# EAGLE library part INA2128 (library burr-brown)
Dual Instrumentation Amplifier Low Power
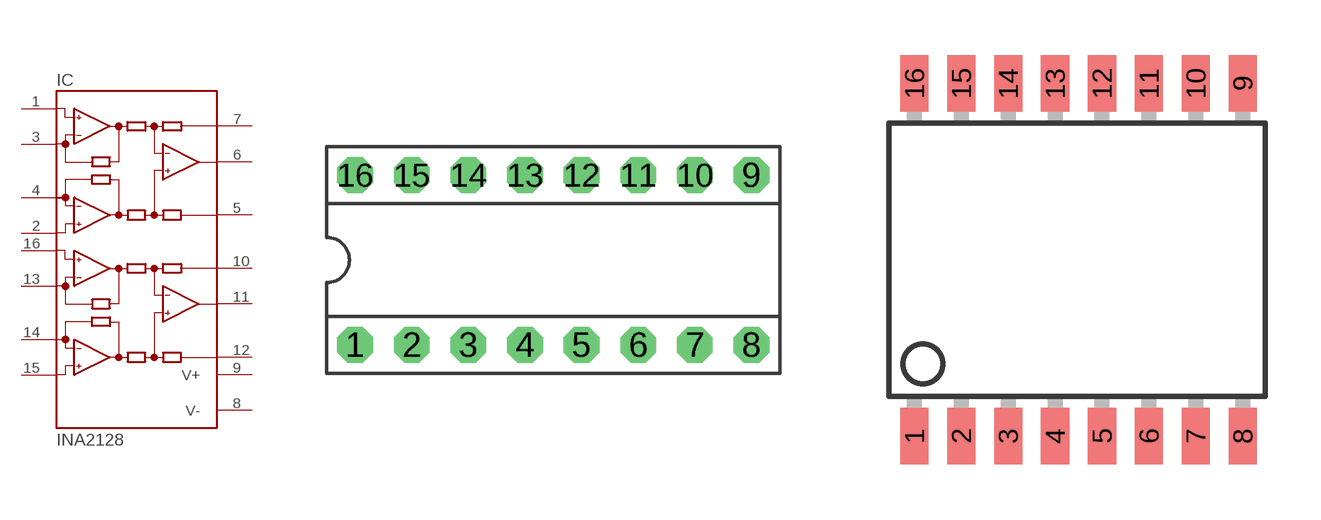
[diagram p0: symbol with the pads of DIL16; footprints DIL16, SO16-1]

Designator prefix IC

## INA2128P (OC_FARNELL: unknown; OC_NEWARK: unknown)  [DIL16]
1  INA-  in
2  INA+  in
3  RGA  pas
4  RGA  pas
5  REFA  in
6  VOA  out
7  SENSEA  in
8  V-  pwr
9  V+  pwr
10  SENSEB  in
11  VOB  out
12  REFB  in
13  RGB  pas
14  RGB  pas
15  INB+  in
16  INB-  in

## INA2128U (MF: TEXAS INSTRUMENTS; MPN: INA2128U; OC_FARNELL: 1212421; OC_NEWARK: 28C7388)  [SO16-1]
Pads as for DIL16

## Footprint DIL16 (pad centres in mm)
Dual In Line
drill 0.813 pad 1.6 octagon: 1 -8.89,-3.81; 2 -6.35,-3.81; 3 -3.81,-3.81; 4 -1.27,-3.81; 5 1.27,-3.81; 6 3.81,-3.81; 7 6.35,-3.81; 8 8.89,-3.81; 9 8.89,3.81; 10 6.35,3.81; 11 3.81,3.81; 12 1.27,3.81; 13 -1.27,3.81; 14 -3.81,3.81; 15 -6.35,3.81; 16 -8.89,3.81

## Footprint SO16-1 (pad centres in mm)
Small Outline Package
smd 0.762 x 1.524: 1 -4.445,-4.775; 2 -3.175,-4.775; 3 -1.905,-4.775; 4 -0.635,-4.775; 5 0.635,-4.775; 6 1.905,-4.775; 7 3.175,-4.775; 8 4.445,-4.775; 9 4.445,4.775; 10 3.175,4.775; 11 1.905,4.775; 12 0.635,4.775; 13 -0.635,4.775; 14 -1.905,4.775; 15 -3.175,4.775; 16 -4.445,4.775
